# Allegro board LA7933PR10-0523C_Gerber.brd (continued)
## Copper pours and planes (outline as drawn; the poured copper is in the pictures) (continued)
+PWR_SRC on BOTTOM (solid shape): 191.74,50.61 191.74,48.07 191.62,47.94 191.54,47.94 190.17,47.94 190.17,47.94 189.84,47.94 188.57,46.67 184.89,46.67 184.38,46.17 182.42,46.17 182.28,46.3 182.28,49.53 188.31,49.53 188.32,49.47 188.33,49.42 188.35,49.37 188.38,49.32 188.41,49.28 188.45,49.24 188.5,49.2 188.55,49.18 188.6,49.16 188.65,49.15 188.71,49.15 188.76,49.15 188.82,49.17 188.87,49.19 188.92,49.22 188.96,49.26 189,49.3 189.03,49.34 189.05,49.39 189.07,49.45 189.08,49.5 189.08,49.56 189.07,49.61 189.05,49.67 189.03,49.72 189,49.76 188.96,49.81 188.92,49.84 188.87,49.87 188.82,49.89 188.76,49.91 188.71,49.91 188.65,49.91 188.6,49.9 188.55,49.88 188.5,49.86 188.45,49.82 188.41,49.79 188.38,49.74 188.35,49.69 188.33,49.64 188.32,49.59 188.31,49.53 182.28,49.53 182.28,49.91 183.11,50.74 191.62,50.74
+PWR_SRC on BOTTOM (solid shape): 145.68,109.1 145.68,107.13 145.49,106.94 145.47,106.94 145.34,106.81 145.34,106.81 145.3,106.76 144.18,106.76 144,106.94 142.98,106.94 142.47,106.43 142.47,104.97 141.71,104.21 136.36,104.21 136.33,104.18 133.4,104.18 132.68,104.91 132.68,107.94 132.83,108.09 144.64,108.09 144.64,108.03 144.65,107.98 144.67,107.93 144.7,107.88 144.74,107.84 144.78,107.8 144.82,107.76 144.87,107.74 144.92,107.72 144.98,107.71 145.03,107.71 145.09,107.71 145.14,107.73 145.19,107.75 145.24,107.78 145.28,107.82 145.32,107.86 145.35,107.9 145.38,107.95 145.39,108.01 145.4,108.06 145.4,108.12 145.39,108.17 145.38,108.23 145.35,108.28 145.32,108.32 145.28,108.37 145.24,108.4 145.19,108.43 145.14,108.45 145.09,108.47 145.03,108.47 144.98,108.47 144.92,108.46 144.87,108.44 144.82,108.42 144.78,108.38 144.74,108.35 144.7,108.3 144.67,108.25 144.65,108.2 144.64,108.15 144.64,108.09 132.83,108.09 133.13,108.39 135.59,108.39 136.85,109.65 145.13,109.65
+PWR_SRC on BOTTOM (solid shape): 24.74,147.64 24.74,147.1 24.72,147 24.74,146.9 24.74,144.84 24.32,144.42 19.03,144.42 19,144.43 18.99,144.44 18.73,144.56 18.45,144.47 18.39,144.45 18.07,144.57 17.75,144.45 17.69,144.47 17.28,144.53 17.05,144.19 17.05,144.17 17.05,143.57 16.99,143.51 16.18,143.51 16.16,143.52 16.16,144.06 16.69,144.06 16.71,144.08 16.71,144.81 16.22,144.81 16.17,144.85 16.17,145.28 16.7,145.28 16.72,145.3 16.72,145.31 16.72,146.05 16.18,146.05 16.16,146.07 16.16,146.81 16.22,146.87 17.13,146.87 17.24,146.75 17.25,146.73 17.36,146.48 17.61,146.37 17.63,146.37 17.75,146.24 19.66,146.24 21.18,147.77 24.61,147.77
+PWR_SRC on BOTTOM (solid shape): outline of 220 points within 181.84,16.19 192.63,25.97
+PWR_SRC on VCC (solid shape): outline of 800 points within 16.86,12.76 198.98,153.23
+PWR_SRC on IN2 (solid shape): outline of 3546 points within 23.34,140.77 79.34,151.12
+PWR_SRC on IN4 (solid shape): outline of 1805 points within 182.22,19.97 266.51,59.26
+PWR_SRC_MXM on TOP (solid shape): 188.9,173.15 188.9,167.89 188.62,167.62 186.64,167.62 185.55,168.71 185.55,174.24 185.79,174.49 187.56,174.49
+PWR_SRC_MXM on TOP (solid shape): 191.24,53.53 191.24,50.48 190.85,50.1 187.4,50.1 185.89,51.61 184.64,51.61 184.38,51.88 184.38,52.64 184.5,52.77 186.02,52.77 187.03,53.79 190.98,53.79
+PWR_SRC_MXM on BOTTOM (solid shape): 188.95,171.46 188.95,167.96 188.7,167.7 187.15,167.7 187.06,167.79 187.06,168.18 186.76,168.47 185.01,168.47 184.89,168.59 184.89,168.99 184.89,168.99 184.89,171.82 185.22,172.15 185.71,172.15 185.85,172.29 188.12,172.29
+PWR_SRC_MXM on BOTTOM (solid shape): outline of 241 points within 184.25,51.37 192.51,58.36
+PWR_SRC_MXM on IN1 (solid shape): outline of 13833 points within 184.5,49.8 221.94,173.2
+SDC_IN on TOP (solid shape): outline of 169 points within 3.15,85.59 12.79,93.54
+USB1_REPEATER_VDD on BOTTOM (solid shape): 262.5,67.51 262.5,67.24 262.49,67.2 262.45,67.19 261.97,67.19 261.97,66.75 262.45,66.75 262.49,66.74 262.5,66.7 262.5,66 261.6,65.1 261.6,63.8 261.39,63.58 260.62,63.58 259.59,64.61 259.59,67.45 259.8,67.66 262.36,67.66
+USB2_REPEATER_VDD on BOTTOM (solid shape): 254.65,69.25 254.65,68.31 255.16,67.8 256.86,67.8 257.79,68.73 258.33,68.73 258.53,68.53 258.53,67.93 257.24,66.64 257.24,66.21 256.97,65.94 255.82,65.94 255.14,65.26 255.14,63.62 255.55,63.21 257,63.21 257.42,62.78 257.42,61.72 257.19,61.48 255.41,61.48 254.15,62.74 254.15,66.6 254.17,66.63 254.2,66.65 254.68,66.65 254.68,67.08 254.2,67.08 254.17,67.1 254.15,67.13 254.15,68.01 254.12,68.04 253.26,68.9 252.83,68.9 252.79,68.94 252.79,69.49 252.83,69.53 254.37,69.53
+V_DDR_REF on BOTTOM (solid shape): 233.01,49.85 233.01,48.71 231.8,47.5 231.8,46.59 231.76,46.55 231.64,46.55 231.61,46.58 231.61,48.13 232.31,48.83 232.31,49.91 232.37,49.98 232.88,49.98
+VCHGR on TOP (solid shape): 188.7,32.58 188.7,31.69 188.57,31.56 186.92,31.56 186.79,31.43 186.79,30.8 186.92,30.67 188.67,30.67 188.69,30.65 188.7,30.63 188.86,30.36 189.16,30.3 189.17,30.3 189.2,30.29 189.84,29.66 189.84,22.67 190.47,22.04 192,22.04 192.12,21.91 192.12,17.21 191.87,16.96 188.57,16.96 188.31,17.21 188.31,20.64 185.39,23.56 185.39,32.58 185.52,32.7 188.57,32.7
+VCHGR_B on TOP (solid shape): 191.87,46.8 191.87,38.67 191.62,38.42 185.65,38.42 185.52,38.55 185.52,46.1 186.47,47.05 191.62,47.05
+VCHGR_B on BOTTOM (solid shape): 190.6,41.85 190.6,38.55 191.24,37.91 191.24,32.32 190.98,32.07 185.9,32.07 185.77,32.2 185.77,41.85 186.03,42.1 190.35,42.1
+VCHGR_L on TOP (solid shape): 192.63,37.91 192.63,32.32 192.25,31.94 192.25,30.16 192,29.91 189.84,29.91 189.58,30.16 189.58,30.42 189.71,30.54 191.24,30.54 191.36,30.67 191.36,31.31 191.24,31.43 189.63,31.43 189.6,31.45 189.58,31.48 189.58,32.83 189.33,33.08 187.3,33.08 187.04,33.34 187.04,37.91 187.17,38.04 192.51,38.04
+VDISPLAY_VCC on TOP (solid shape): 36.92,162.48 36.92,159.1 36.12,158.29 36.12,157.39 35.46,156.73 34.8,156.73 34.79,156.76 34.76,156.8 34.72,156.84 34.68,156.87 34.63,156.9 34.58,156.92 34.52,156.93 34.47,156.94 34.41,156.93 34.36,156.92 34.31,156.9 34.26,156.87 34.21,156.84 34.17,156.8 34.14,156.76 34.13,156.73 31.68,156.73 31.1,157.32 31.1,159.03 34.1,159.03 34.1,158.97 34.11,158.92 34.13,158.87 34.16,158.82 34.19,158.77 34.23,158.74 34.28,158.7 34.33,158.68 34.38,158.66 34.44,158.65 34.49,158.65 34.55,158.65 34.6,158.67 34.65,158.69 34.7,158.72 34.74,158.75 34.78,158.8 34.81,158.84 34.84,158.89 34.85,158.95 34.86,159 34.86,159.06 34.85,159.11 34.84,159.17 34.81,159.22 34.78,159.26 34.74,159.31 34.7,159.34 34.65,159.37 34.6,159.39 34.55,159.41 34.49,159.41 34.44,159.41 34.38,159.4 34.33,159.38 34.28,159.36 34.23,159.32 34.19,159.29 34.16,159.24 34.13,159.19 34.11,159.14 34.1,159.09 34.1,159.03 31.1,159.03 31.1,160.06 31.46,160.41 34.29,160.41 34.56,160.68 34.56,162.37 34.91,162.73 36.68,162.73
+VDISPLAY_VCC on IN2 (solid shape): outline of 196 points within 35.44,161.56 38.85,170.05
+VDISPLAY_VCC on IN3 (solid shape): outline of 196 points within 35.44,161.56 38.85,170.05
BOOT on TOP (solid shape): 179.3,37.78 179.3,37.02 179.11,36.83 178.54,36.83 177.48,35.78 176.86,35.78 176.5,35.42 176.5,33.33 176.49,33.29 176.45,33.27 176.3,33.27 176.26,33.29 176.25,33.33 176.25,36.51 176.44,36.7 177.46,36.7 177.96,37.21 177.96,37.85 178.03,37.91 179.17,37.91
BOOT1 on TOP (solid shape): 28.99,76.71 28.99,76.26 29.25,76.01 30.25,76.01 31.41,76.01 31.91,76.52 32.49,76.52 32.61,76.39 32.61,75.38 32.36,75.12 29.95,75.12 29.56,75.5 29.1,75.5 28.74,75.86 28.74,76.71 28.8,76.77 28.93,76.77
BOOT1G on TOP (solid shape): 31.34,84.46 31.34,83.25 28.99,80.9 28.8,80.9 28.8,81.73 28.93,81.85 29.31,81.85 30.2,82.74 30.2,83.88 30.07,84.01 30.07,84.52 30.2,84.65 31.15,84.65
BOOT2 on TOP (solid shape): 32.54,83.13 32.54,82.16 32.36,81.98 30.83,81.98 30.01,81.15 30.01,80.77 30.07,80.71 30.07,80.58 30.01,80.52 29.12,80.52 29.06,80.58 29.06,80.65 29.12,80.71 29.18,80.71 29.37,80.9 29.37,81.09 31.53,83.25 32.42,83.25
BOOT2G on TOP (solid shape): 27.99,88.77 28.07,88.77 28.57,88.27 29.31,88.27 29.39,88.19 29.39,88.08 29.31,88 28.41,88 28.14,88.27 27.76,88.27 27.7,88.33 26.77,88.33 26.52,88.58 26.52,88.96 26.85,89.29 27.47,89.29
BOOT3 on BOTTOM (solid shape): 49.06,45.15 49.06,44.32 48.93,44.2 47.8,44.2 47.55,44.45 45.95,44.45 45.88,44.51 45.88,44.71 45.95,44.77 46.96,44.77 47.47,45.28 48.93,45.28
BOOT_1.5V on BOTTOM (solid shape): 229.2,45.66 230.26,45.66 230.27,45.64 230.27,45.44 230.23,45.4 228.48,45.4 228.18,45.1 228.18,44.34 228,44.16 227.29,44.16 227.16,44.29 227.16,45.5 227.37,45.71 229.14,45.71
BST1_3V on BOTTOM (solid shape): 283.63,60.52 283.63,57.66 283.5,57.53 282.68,57.53 282.48,57.72 282.48,60.58 282.61,60.71 283.44,60.71
BST1_5V on BOTTOM (solid shape): 270.42,61.34 270.42,58.61 270.17,58.36 269.53,58.36 269.34,58.55 269.34,61.28 269.53,61.47 270.29,61.47
BST_3V on BOTTOM (solid shape): 282.04,60.45 282.04,59.44 281.91,59.31 280.45,59.31 280.12,59.65 280.12,60.23 279.96,60.39 277.79,60.39 277.72,60.45 277.72,60.58 277.79,60.64 281.85,60.64
BST_5V on BOTTOM (solid shape): 273.21,60.64 274.67,60.64 274.67,60.39 271.98,60.39 271.73,60.14 270.99,60.14 270.86,60.26 270.86,61.34 270.99,61.47 272.39,61.47
BST_+V1.05S_VCCPP on BOTTOM (solid shape): 61.43,22.81 61.44,22.8 61.44,22.78 61.44,22.66 62.08,22.02 62.08,20.32 61.95,20.19 61.12,20.19 60.87,20.45 60.87,22.29 60.49,22.67 60.49,22.92 60.55,22.99 61.25,22.99
BST_+V1.05SP on TOP (solid shape): 5.88,152.02 5.88,151.89 6.83,150.94 7.15,150.94 7.34,150.75 7.34,150.11 7.15,149.92 6.2,149.92 6.07,150.05 6.07,150.44 6.2,150.57 6.2,151.06 5.99,151.26 5.61,151.26 5.56,151.31 5.56,152.08 5.62,152.15 5.75,152.15
CD3301_DCIN on TOP (solid shape): 175.02,69.85 175.02,68.5 174.96,68.45 174.96,68.09 174.79,67.92 174.79,66.68 174.41,66.29 171.42,66.29 171.3,66.42 171.3,67.5 171.49,67.69 173.58,67.69 174.73,68.83 174.73,69.86 174.78,69.91 174.95,69.91
CHG_LGATE on BOTTOM (solid shape): 193.52,35.24 193.52,34.99 193.52,34.9 193.6,34.82 194.26,34.82 194.33,34.75 194.33,34.09 194.21,33.96 193.56,33.96 192.66,34.86 191.87,34.86 191.74,34.99 191.74,35.24 191.87,35.37 193.39,35.37
CHG_SNUB on BOTTOM (solid shape): 193.39,33.72 195.72,33.72 195.78,33.66 195.78,32.69 195.53,32.44 193.25,32.44 192.89,32.07 192.12,32.07 191.87,32.32 191.87,33.85 192.12,34.1 193.01,34.1
CHG_UGATE on BOTTOM (solid shape): 190.09,43.12 190.09,42.48 189.97,42.36 186.28,42.36 186.16,42.48 186.16,43.12 186.28,43.24 189.97,43.24
CHG_UGATE on BOTTOM (solid shape): 177.39,36.16 177.39,34.56 177.27,34.43 176.6,34.43 176.48,34.56 176.48,36.16 176.55,36.23 177.32,36.23
DH_1.5V on BOTTOM (solid shape): 221.7,41.17 221.7,39.9 221.58,39.78 220.56,39.78 220.31,40.03 220.31,41.17 220.43,41.3 221.58,41.3
DH_1.5V on BOTTOM (solid shape): 229.29,45.24 230.25,45.24 230.27,45.22 230.27,45.05 230.23,45.01 229.31,45.01 228.94,44.64 228.94,44.63 228.94,44.2 228.88,44.13 228.43,44.13 228.37,44.2 228.37,45.02 228.62,45.28 229.26,45.28
DH_1.5V on IN3 (solid shape): 229.17,45.5 229.17,44.36 228.92,44.11 227.9,44.11 227.65,44.36 227.65,45.5 227.77,45.63 229.04,45.63
DH_1.5V on IN3 (solid shape): 221.89,41.49 221.89,40.07 221.73,39.9 220.69,39.9 220.43,40.16 220.43,41.44 220.79,41.8 221.59,41.8
DL_1.5V on BOTTOM (solid shape): 222.99,35.68 222.99,33.54 222.86,33.42 221.5,33.42 221.42,33.49 221.42,35.66 221.72,35.95 222.72,35.95
DL_1.5V on BOTTOM (solid shape): 230.61,44.49 230.61,43.58 230.34,43.31 230.34,42.18 230.34,42.17 230.34,41.78 230.27,41.72 229.32,41.72 229.2,41.85 229.2,42.93 230.4,44.13 230.4,44.49 230.44,44.54 230.56,44.54
DL_1.5V on IN1 (solid shape): 223.32,34.82 223.32,33.89 223.11,33.68 221.68,33.68 221.51,33.84 221.51,34.8 221.65,34.94 223.2,34.94
DL_1.5V on IN1 (solid shape): 230.34,42.55 230.34,41.4 230.21,41.28 228.56,41.28 228.5,41.34 228.5,42.42 228.69,42.61 229.51,42.61 229.58,42.67 230.21,42.67
ERC1 on TOP (solid shape): 176,68.75 176.12,68.62 176.12,67.19 176.25,67.06 176.25,66.49 176.12,66.36 175.17,66.36 174.98,66.55 174.98,67.17 175.86,68.05 175.86,68.61 175.74,68.72 175.74,69.72 176,69.72
ERC3 on TOP (solid shape): 182.35,71.37 182.35,70.23 182.12,70 181.41,70 181.28,70.13 181.28,70.76 180.99,71.05 180.7,71.05 180.69,71.06 179.23,71.06 179.23,71.31 180.88,71.31 181.08,71.5 182.22,71.5
GP1_SW on TOP (solid shape): 46.58,84.29 46.58,81.27 46.46,81.14 45.19,81.14 45.06,81.01 45.06,80.76 45.19,80.63 46.46,80.63 46.58,80.5 46.58,79.69 46.46,79.57 43.41,79.57 43.15,79.82 43.15,80.76 42.9,81.01 41.5,81.01 41.38,81.14 41.38,84.44 41.57,84.63 46.24,84.63
GP2_SW on TOP (solid shape): 46.71,90.75 46.71,88.63 46.58,88.5 45.06,88.5 45.06,88 46.58,88 46.71,87.87 46.71,87.06 46.54,86.89 43.56,86.89 43.47,86.98 41.5,86.98 41.38,87.11 41.38,90.77 41.53,90.93 46.54,90.93
LG_3V on BOTTOM (solid shape): 279.25,58.61 279.25,58.36 279.12,58.23 278.17,58.23 277.72,58.67 277.72,59.06 277.79,59.12 278.74,59.12
LG_3V on BOTTOM (solid shape): 276.05,49.4 276.05,48.32 275.99,48.27 274.13,48.27 274.04,48.36 274.04,49.29 274.22,49.47 275.98,49.47
LG_3V on IN3 (solid shape): 276.58,49.47 276.58,48.71 276.45,48.58 274.17,48.58 274.04,48.71 274.04,49.59 274.17,49.72 276.33,49.72
LG_3V on IN3 (solid shape): 279.37,58.48 279.37,57.72 279.25,57.6 277.98,57.6 277.85,57.72 277.85,58.74 277.98,58.87 278.99,58.87
LG_5V on BOTTOM (solid shape): 270.1,46.42 270.1,45.66 269.9,45.45 268.88,45.45 268.68,45.66 267.79,45.66 267.51,45.94 267.51,46.58 267.6,46.67 269.85,46.67
LG_5V on BOTTOM (solid shape): 274.74,59.11 274.74,58.87 274.61,58.74 274.61,58.23 274.55,58.17 273.47,58.17 273.4,58.23 273.4,58.9 273.67,59.17 274.67,59.17
LG_5V on IN3 (solid shape): 274.67,58.61 274.67,57.47 274.55,57.34 273.4,57.34 273.28,57.47 273.28,58.61 273.4,58.74 274.55,58.74
LG_5V on IN3 (solid shape): 270.1,46.8 270.1,45.66 269.9,45.45 268.78,45.45 268.58,45.66 268.58,46.93 268.71,47.05 269.85,47.05
LG_+V1.05S_VCCPP on TOP (solid shape): 67.05,20.77 67.05,20.02 66.97,19.93 65.75,19.93 65.61,20.07 65.61,20.74 65.76,20.89 66.93,20.89
LG_+V1.05S_VCCPP on BOTTOM (solid shape): 61.76,25.59 61.76,25.15 61.31,24.7 60.55,24.7 60.45,24.8 60.45,25.53 60.58,25.65 61.7,25.65
LG_+V1.05S_VCCPP on BOTTOM (solid shape): 67.41,20.21 67.41,19.5 67.28,19.37 65.4,19.37 65.33,19.44 65.33,19.93 66,20.6 67.02,20.6
LG_+V1.05SP on TOP (solid shape): 3.85,152.08 3.85,151.45 3.78,151.38 2.36,151.38 2.26,151.49 2.26,152.07 2.34,152.15 3.78,152.15
LG_+V1.05SP on BOTTOM (solid shape): 9.09,141.58 9.09,140.17 9.07,140.15 8.49,140.15 7.86,140.78 6.96,140.78 6.83,140.91 6.83,141.29 6.96,141.42 7.82,141.42 8.04,141.64 8.69,141.64 8.72,141.68 9,141.68
LG_+V1.05SP on IN1 (solid shape): 3.44,152.02 3.44,151.36 3.14,151.05 1.81,151.05 1.33,151.54 1.33,152.13 1.56,152.36 3.1,152.36
LG_+V1.05SP on IN1 (solid shape): 9.1,141.55 9.1,141.19 8.65,140.73 7.55,140.73 7.47,140.82 7.47,141.33 7.73,141.59 8.56,141.59 8.66,141.69 8.96,141.69
LGATE1 on TOP (solid shape): 43.03,62.85 43.03,61.96 42.9,61.83 41.5,61.83 41.38,61.96 41.38,62.85 41.5,62.98 42.9,62.98
LGATE1 on TOP (solid shape): 43.79,56.88 43.79,56.12 43.66,55.99 41.5,55.99 41.38,56.12 41.38,56.88 41.5,57.01 43.66,57.01
LGATE1 on TOP (solid shape): 30.52,77.72 30.89,77.72 31.48,77.72 31.52,77.71 31.53,77.67 31.53,77.22 31.47,77.15 30.64,77.15 30.07,77.72 29.17,77.72 29.13,77.74 29.12,77.78 29.12,77.86 29.13,77.9 29.17,77.92 30.33,77.92
LGATE1 on BOTTOM (solid shape): 43.78,57.72 43.78,56.59 43.62,56.44 42.65,56.44 42.45,56.63 42.45,57.54 42.71,57.8 43.7,57.8
LGATE1 on BOTTOM (solid shape): 43.09,62.97 43.09,62 42.96,61.87 41.64,61.87 41.54,61.98 41.54,62.95 41.6,63.02 43.04,63.02
LGATE1 on IN1 (solid shape): 43.4,63.57 43.4,62.67 43.41,62.66 43.41,57.72 43.92,57.21 43.92,56.58 43.71,56.37 41.88,56.37 41.76,56.5 41.76,63.56 42.01,63.82 43.15,63.82
LGATE1 on IN1 (solid shape): 30.51,77.78 30.71,77.72 30.92,77.79 32.23,77.79 32.36,77.66 32.36,77.03 32.23,76.9 30.45,76.9 30.33,77.03 30.33,77.66 30.45,77.79 30.49,77.79
LGATE1G on TOP (solid shape): 28.17,83.5 28.17,82.55 27.85,82.23 27.85,81.79 27.72,81.66 27.72,80.9 27.6,80.9 27.6,83.44 27.72,83.57 28.1,83.57
LGATE1G on TOP (solid shape): 42.61,80.53 42.59,80.52 42.59,79.31 42.39,79.11 41.5,79.11 41.38,79.23 41.38,80.5 41.5,80.63 42.51,80.63
LGATE1G on BOTTOM (solid shape): 42.51,80.35 42.51,79.11 42.4,79.01 41.55,79.01 41.38,79.19 41.38,80.37 41.53,80.52 42.34,80.52
LGATE1G on IN3 (solid shape): 42.65,79.74 42.65,78.85 42.52,78.73 40.49,78.73 40.36,78.85 40.36,79.74 40.49,79.87 42.52,79.87
LGATE1G on IN3 (solid shape): 28.56,84.51 28.56,83.83 28.17,83.44 28.17,82.49 28.04,82.36 27.66,82.36 27.57,82.45 27.55,82.48 27.56,82.51 27.6,82.7 27.53,82.89 27.53,83.29 27.7,83.45 27.7,83.88 27.53,84.05 27.53,84.77 27.66,84.9 28.17,84.9
LGATE2 on TOP (solid shape): 42.65,74.41 42.65,73.14 42.52,73.01 41.38,73.01 41.25,73.14 41.25,74.41 41.38,74.53 42.52,74.53
LGATE2 on TOP (solid shape): 42.65,68.49 42.65,67.17 42.52,67.04 41.38,67.04 41.25,67.17 41.25,67.88 41.25,67.88 41.25,68.48 41.48,68.71 42.42,68.71
LGATE2 on TOP (solid shape): 31.6,79.76 31.6,79.5 31.47,79.38 30.96,79.38 30.83,79.25 30.45,79.25 30.39,79.31 29.12,79.31 29.12,79.5 30.33,79.5 30.71,79.88 31.47,79.88
LGATE2 on BOTTOM (solid shape): 42.58,68.47 42.58,67.26 42.4,67.08 41.46,67.08 41.25,67.3 41.25,68.44 41.38,68.57 42.48,68.57
LGATE2 on BOTTOM (solid shape): 43.41,73.75 43.41,72.75 43.18,72.52 41.62,72.52 41.16,72.97 41.16,73.83 41.21,73.88 43.28,73.88
LGATE2 on IN1 (solid shape): 42.65,73.39 42.65,67.3 42.39,67.04 41.25,67.04 41.12,67.17 41.12,72.63 40.99,72.76 40.23,72.76 40.11,72.88 40.11,73.52 40.23,73.65 42.39,73.65
LGATE2 on IN1 (solid shape): 32.8,79.44 32.8,78.99 32.68,78.87 32.1,78.87 31.6,79.38 30.96,79.38 30.83,79.25 30.52,79.25 30.39,79.38 30.39,79.76 30.52,79.88 32.36,79.88
LGATE2G on TOP (solid shape): 42.65,86.59 42.65,85.34 42.52,85.2 41.5,85.2 41.38,85.33 41.38,86.6 41.5,86.73 42.52,86.73
LGATE2G on TOP (solid shape): 31.72,87.16 31.72,86.36 31.6,86.23 30.45,86.23 30.33,86.36 30.33,86.59 30.55,86.82 30.55,86.93 30.55,86.94 30.55,87.21 30.66,87.31 31.57,87.31
LGATE2G on BOTTOM (solid shape): 42.81,86.37 42.81,85.32 42.63,85.14 41.69,85.14 41.51,85.32 41.51,85.64 41.57,85.69 41.81,85.69 41.91,85.79 41.91,86.39 41.96,86.44 42.75,86.44
LGATE2G on IN3 (solid shape): 42.65,85.84 42.65,84.95 42.52,84.82 40.87,84.82 40.74,84.95 40.74,85.84 40.87,85.96 42.52,85.96
LGATE2G on IN3 (solid shape): 32.61,87.06 32.61,86.31 32.57,86.23 32.48,86.21 32.23,86.21 32.04,86.07 32.02,86.05 32,86.04 30.45,86.04 30.33,86.17 30.33,87.19 30.45,87.31 32.36,87.31
LGATE3 on TOP (solid shape): 52.04,54.62 52.04,53.7 51.79,53.45 50.65,53.45 50.39,53.71 50.39,54.43 50.65,54.69 51.97,54.69
LGATE3 on TOP (solid shape): 46.33,54.64 46.33,53.83 46.07,53.58 44.8,53.58 44.68,53.71 44.68,54.6 44.95,54.87 46.09,54.87
LGATE3 on BOTTOM (solid shape): 51.93,54.48 51.93,53.63 51.57,53.28 50.79,53.28 50.72,53.34 50.72,54.24 51.1,54.62 51.79,54.62
LGATE3 on BOTTOM (solid shape): 44.74,43.75 44.74,43.31 44.68,43.24 44.3,43.24 43.89,42.84 43.32,42.84 43.03,43.13 43.03,43.75 43.09,43.82 44.68,43.82
LGATE3 on BOTTOM (solid shape): 46.71,55.07 46.71,53.98 46.43,53.7 45.77,53.7 45.6,53.86 45.6,54.09 45.4,54.29 44.82,54.29 44.65,54.46 44.65,55.19 44.72,55.26 46.52,55.26
LGATE3 on IN1 (solid shape): 44.11,44.13 44.11,42.98 43.97,42.84 43.17,42.84 42.92,43.08 42.92,44.06 43.09,44.22 44.02,44.22
LGATE3 on IN1 (solid shape): 52.11,54.74 52.11,53.59 51.92,53.4 51.22,53.4 50.96,53.66 46.71,53.66 46.52,53.47 46.52,52.71 46.39,52.58 45.57,52.58 45.44,52.71 45.44,54.86 45.57,54.99 51.85,54.99
LX_3V on TOP (solid shape): 283.89,50.32 283.89,49.87 283.31,49.29 281.91,49.29 281.77,49.43 281.77,49.78 282.36,50.37 283.84,50.37
LX_3V on TOP (solid shape): 282.81,57.06 282.81,56.6 282.51,56.3 281.75,56.3 281.01,57.04 281.01,57.42 281.14,57.54 282.33,57.54
LX_3V on BOTTOM (solid shape): 280.01,58.93 282.08,58.93 282.23,58.78 282.23,57.05 282.12,56.93 281.11,56.93 278.67,59.37 277.79,59.37 277.72,59.44 277.72,59.56 277.79,59.63 279.31,59.63
LX_3V on BOTTOM (solid shape): 285.34,51.63 285.34,48.83 286.61,47.56 286.61,44.26 285.64,43.29 278.53,43.29 277.89,43.93 276.82,43.93 276.58,44.17 276.58,48.96 276.71,49.09 281.53,49.09 281.66,49.21 281.66,50.36 281.53,50.48 280.39,50.48 280.14,50.74 280.14,52.39 280.39,52.64 284.33,52.64
LX_5V on TOP (solid shape): 264.83,51.36 264.83,50.25 264.64,50.06 263.97,50.06 263.76,50.27 263.76,51.35 263.9,51.49 264.7,51.49
LX_5V on TOP (solid shape): 272.93,59.33 272.93,58.84 272.16,58.06 271.55,58.06 271.5,58.12 271.5,58.94 272,59.44 272.82,59.44
LX_5V on BOTTOM (solid shape): 274.78,59.56 274.78,59.45 274.72,59.4 273.68,59.4 273.53,59.25 273.15,59.25 272.26,58.36 270.99,58.36 270.86,58.48 270.86,59.44 271.05,59.63 274.71,59.63
LX_5V on BOTTOM (solid shape): 265.78,51.88 265.78,49.47 266.17,49.09 266.72,49.09 267.03,48.78 267.03,45.82 266.17,44.96 266.17,41.59 266.04,41.47 262.23,41.47 261.21,42.48 261.21,47.05 260.83,47.44 260.83,51.63 261.21,52.01 265.66,52.01
MAX8731A_LDO on TOP (solid shape): 180.92,32.96 180.96,32.96 181.64,32.96 181.64,32.96 181.89,32.96 182.07,32.78 182.07,31.92 182.47,31.51 182.47,31.13 182.4,31.05 182.16,31.05 182.14,31.03 181.46,31.03 180.95,31.53 180.95,31.76 180.95,31.76 180.95,32.12 180.95,32.2 180.24,32.91 179.55,32.91 179.35,32.7 178.33,32.7 178.3,32.72 178.28,32.75 178.28,32.88 178.3,32.92 178.33,32.93 179.04,32.93 179.5,33.39 180.49,33.39
Net_85 on TOP (solid shape): 282.95,10.62 282.95,6.87 283.07,6.75 283.07,2.28 282.98,2.19 282.22,2.19 282.06,2.35 282.06,6.69 282.16,6.79 282.16,10.67 282.17,10.68 282.89,10.68
P1_SW on TOP (solid shape): 46.58,67.93 46.58,66.79 46.46,66.66 45.31,66.66 45.19,66.53 45.19,66.28 45.31,66.15 46.46,66.15 46.58,66.03 46.58,65.06 46.55,64.99 46.48,64.96 46.33,64.94 46.2,64.87 46.14,64.84 46.07,64.87 45.55,64.85 45.53,64.33 45.56,64.26 45.53,64.2 45.84,63.56 46.08,64.23 46.06,64.26 46.08,64.3 46.1,64.32 46.14,64.34 46.17,64.32 46.31,64.23 46.48,64.2 46.55,64.17 46.58,64.1 46.58,61.07 46.33,60.82 43.61,60.82 43.53,60.82 43.28,60.56 43.28,57.64 43.03,57.39 41.63,57.39 41.38,57.64 41.38,61.15 41.93,61.71 43.03,61.71 43.15,61.83 43.15,63.1 43.03,63.23 41.5,63.23 41.38,63.36 41.38,66.66 41.5,66.79 42.77,66.79 42.9,66.91 42.9,67.93 43.03,68.06 46.46,68.06
P2_SW on TOP (solid shape): outline of 133 points within 41.25,68.62 46.71,78.78
P3_SW on TOP (solid shape): 46.46,60.52 46.46,59.75 46.38,59.68 45.57,59.68 45.31,59.42 45.31,59.04 45.44,58.91 46.28,58.91 46.46,58.74 46.46,57.39 46.65,57.2 48.55,57.2 49.63,56.12 49.66,56.03 49.6,55.96 49.4,55.47 49.88,55.25 49.97,55.23 50.01,55.15 50.01,53.71 49.88,53.58 46.58,53.58 46.46,53.71 46.46,53.78 46.46,54.77 46.19,55.04 44.86,55.04 44.3,54.47 44.3,53.83 44.04,53.58 40.99,53.58 40.74,53.83 40.74,55.48 40.99,55.74 43.84,55.74 44.04,55.94 44.04,56.83 43.41,57.47 43.41,60.41 43.41,60.44 43.66,60.69 46.28,60.69
PBATT+ on TOP (solid shape): outline of 191 points within 181.58,5.02 188.06,21.91
PBATT+_C on TOP (solid shape): 191.24,10.1 191.24,8.7 191.11,8.57 190.35,8.57 190.22,8.45 190.22,7.05 190.35,6.92 191.49,6.92 191.74,6.67 191.74,5.53 192.12,5.14 192.12,1.59 191.87,1.33 187.93,1.33 187.81,1.46 187.81,5.34 187.81,5.35 187.81,10.1 188.06,10.35 190.98,10.35
PBATT_IN_SS on TOP (solid shape): 195.3,16.07 195.3,11.24 194.92,10.86 187.55,10.86 187.17,11.24 187.17,16.07 187.43,16.32 195.05,16.32
PBATT_IN_SS on BOTTOM (solid shape): 194.16,19.11 194.16,18.23 195.05,17.34 196.32,17.34 196.44,17.21 196.44,11.24 196.06,10.86 184.63,10.86 184.25,11.24 184.25,15.56 184.63,15.94 188.31,15.94 189.2,16.83 189.2,18.99 189.58,19.37 193.9,19.37
PHASE1 on TOP (solid shape): 35.67,62.85 36.93,62.85 37.06,62.72 37.06,62.09 36.93,61.96 35.02,61.96 34.77,62.21 34.77,62.72 34.99,62.94 35.58,62.94
PHASE1 on TOP (solid shape): 37.06,57.14 37.06,56.25 36.8,55.99 35.41,55.99 35.39,56.01 34.99,56.01 34.82,56.19 34.82,57.18 34.9,57.26 36.93,57.26
PHASE1 on TOP (solid shape): 32.68,77.85 32.68,76.96 32.42,76.71 31.72,76.71 31.6,76.58 31.6,76.39 31.41,76.2 30.58,76.2 30.39,76.39 30.39,76.63 30.2,76.82 30.2,77.08 30.14,77.14 30.14,77.15 30.01,77.28 29.17,77.28 29.13,77.29 29.12,77.33 29.12,77.42 29.13,77.46 29.17,77.47 30.14,77.47 30.3,77.31 30.3,77.3 30.37,77.2 30.47,77.13 30.48,77.13 30.58,77.03 31.53,77.03 31.66,77.15 31.66,77.85 31.85,78.04 32.49,78.04
PHASE1 on IN1 (solid shape): 37.23,62.59 37.23,56.23 36.68,55.67 34.42,55.67 34.03,56.06 34.03,57.07 34.26,57.3 35.81,57.3 36.04,57.53 36.04,60.11 36.07,60.25 36.04,60.39 36.04,61.14 35.84,61.34 34.68,61.34 34.5,61.52 34.5,62.53 34.69,62.72 37.1,62.72
PHASE1 on IN3 (solid shape): 31.72,76.65 31.72,75.12 31.6,74.99 30.58,74.99 30.45,75.12 30.45,76.65 30.58,76.77 31.6,76.77
PHASE1 on IN3 (solid shape): 35.34,63.63 35.35,63.6 35.34,63.57 35.36,63.13 35.78,63 35.87,62.98 35.91,62.9 35.91,62.17 35.79,62.04 34.9,62.04 34.14,62.8 34.14,63.44 34.39,63.69 35.28,63.69
PHASE1G on TOP (solid shape): 37.06,80.5 37.06,79.74 36.8,79.49 34.64,79.49 34.52,79.61 34.52,80.25 34.64,80.38 35.91,80.38 36.17,80.63 36.93,80.63
PHASE1G on TOP (solid shape): 29.18,84.65 29.18,82.8 28.8,82.42 28.61,82.42 28.17,81.98 28.17,80.9 27.98,80.9 27.98,82.17 28.29,82.49 28.29,83.57 27.85,84.01 27.85,84.52 28.04,84.71 29.12,84.71
PHASE1G on IN4 (solid shape): 29.06,83.5 29.06,83 29.18,82.87 29.82,82.87 29.95,82.74 29.95,81.98 29.82,81.85 28.68,81.85 28.29,82.23 28.29,83.5 28.42,83.63 28.93,83.63
PHASE1G on IN4 (solid shape): 34.52,80.33 35.79,80.33 35.91,80.2 35.91,79.57 35.79,79.44 34.67,79.44 34.42,79.53 34.16,79.44 34.01,79.44 33.5,79.95 33.5,80.46 33.76,80.71 34.14,80.71
PHASE2 on TOP (solid shape): 36.93,68.69 36.93,67.93 36.8,67.8 34.77,67.8 34.52,68.06 34.52,68.69 34.64,68.82 36.8,68.82
PHASE2 on TOP (solid shape): 37.06,74.53 37.06,73.77 36.93,73.65 34.77,73.65 34.64,73.77 34.64,74.53 34.77,74.66 36.93,74.66
PHASE2 on TOP (solid shape): 32.68,81.6 32.68,80.77 32.36,80.46 31.79,80.46 31.34,80.01 30.64,80.01 30.33,79.69 29.12,79.69 29.12,79.88 30.2,79.88 31.28,80.96 31.28,81.66 31.41,81.79 32.49,81.79
PHASE2 on IN3 (solid shape): 32.61,80.65 32.61,80.14 32.49,80.01 30.77,80.01 30.64,80.14 30.64,80.39 31.02,80.77 32.49,80.77
PHASE2 on IN3 (solid shape): 34.3,75.71 34.3,74.98 34.54,74.74 37.06,74.74 37.44,74.36 37.44,68.64 36.55,67.76 36.23,67.76 36.22,67.76 36.04,67.8 35.87,67.76 35.85,67.76 34.78,67.76 34.52,68.02 34.52,68.77 34.64,68.9 35.79,68.9 36.17,69.28 36.17,73.47 35.91,73.72 33.7,73.72 33.02,74.41 33.02,75.69 33.21,75.88 34.12,75.88
PHASE2G on TOP (solid shape): 37.06,86.6 37.06,85.96 36.93,85.84 34.52,85.84 34.39,85.96 34.39,86.85 34.52,86.98 36.68,86.98
PHASE2G on TOP (solid shape): 31.58,90.23 31.58,88.73 31.34,88.49 30.64,88.49 30.55,88.58 30.55,88.77 30.43,88.89 30.03,88.89 29.73,89.19 29.73,89.71 29.56,89.88 29.56,90.74 29.82,91 30.82,91
PHASE2G on IN1 (solid shape): 31.52,89.83 31.52,89.13 31.46,89.07 30.26,89.07 30.06,89.27 30.06,89.78 30.16,89.88 31.47,89.88
PHASE2G on IN1 (solid shape): 35.93,86.82 35.93,86.09 35.86,86.03 34.69,86.03 34.53,86.2 34.53,86.79 34.75,87.01 35.74,87.01
PHASE3 on TOP (solid shape): 51.28,49.13 51.28,46.98 51.15,46.85 50.39,46.85 50.27,46.98 50.27,49.13 50.39,49.26 51.15,49.26
PHASE3 on TOP (solid shape): 45.68,49.09 45.68,47.59 45.59,47.5 44.63,47.5 44.55,47.57 44.55,49.09 44.68,49.21 45.55,49.21
PHASE3 on BOTTOM (solid shape): 46.39,48.07 46.39,47.63 46.17,47.41 46.14,47.37 46.1,47.33 45.57,46.8 45.57,46.48 44.74,45.66 44.74,45.29 44.74,45.09 44.61,44.96 43.85,44.96 43.79,45.02 43.79,46.42 44.55,47.18 44.55,47.88 44.87,48.2 46.27,48.2
PHASE3 on IN3 (solid shape): 50.96,49.21 50.96,46.86 50.9,46.8 50.33,46.8 50.14,46.99 50.14,48.13 50.01,48.26 46.98,48.26 46.07,47.36 44.65,47.36 44.45,47.56 44.45,48.18 44.63,48.36 45.16,48.36 46.14,49.34 50.84,49.34
PWMG2 on TOP (solid shape): 27.47,82.8 27.47,81.85 27.34,81.73 27.34,80.9 27.15,80.9 27.15,82.3 26.96,82.49 26.96,82.87 27.02,82.93 27.34,82.93
PWMG2 on TOP (solid shape): 28.2,87.99 28.2,87.92 28.34,87.77 29.31,87.77 29.37,87.71 29.37,87.55 29.32,87.5 27.51,87.5 27.47,87.54 27.47,87.99 27.61,88.13 28.06,88.13
SNUB_1.5V on BOTTOM (solid shape): 229.75,34.52 229.75,31.38 229.34,30.96 228.01,30.96 227.82,31.15 227.82,34.51 228.08,34.76 229.51,34.76
SNUB_1.5VSP on BOTTOM (solid shape): 211.43,69.03 211.43,68.26 211.3,68.14 207.75,68.14 207.62,68.26 207.62,69.15 207.75,69.28 211.17,69.28
SNUB_3V on BOTTOM (solid shape): 278.69,41.99 278.69,41.48 278.43,41.22 276.78,41.22 275,43 275,43.51 275.26,43.76 276.91,43.76
SNUB_5V on BOTTOM (solid shape): 268.31,45.03 269.71,45.03 269.96,44.78 269.96,43.64 269.84,43.51 267.04,43.51 266.91,43.64 266.91,45.03 267.17,45.29 268.06,45.29
SNUB_+V1.05SP on BOTTOM (solid shape): 8.46,139.89 9.57,139.89 9.57,139.89 11.58,139.89 11.76,139.71 11.76,138.66 11.61,138.51 10.38,138.51 10.01,138.76 9.63,138.51 9.31,138.18 7.31,138.18 6.92,138.57 6.92,139.68 7.31,140.07 8.28,140.07
SW_1.5V on BOTTOM (solid shape): 230.27,44.83 230.27,44.63 230.22,44.58 230.22,44.39 228.28,42.46 227.37,42.46 227.16,42.66 227.16,43.69 227.37,43.9 228.83,43.9 229.07,44.13 229.07,44.58 229.33,44.84 230.26,44.84
SW_1.5V on BOTTOM (solid shape): 224.41,47.75 224.41,44.51 225.61,43.31 225.61,43.07 225.84,42.61 226.35,42.53 226.37,42.54 226.4,42.52 229.8,39.12 229.8,37.07 229.4,36.67 222.36,36.67 222.17,36.86 222.17,41.19 221.83,41.52 219.81,41.52 219.68,41.4 219.68,40.01 219.57,39.9 216.4,39.9 216.08,40.22 216.08,43.23 218.41,45.57 218.41,48.2 219,48.78 223.38,48.78
SW_1.5V on IN4 (solid shape): 229.34,43.79 229.34,43.29 228.59,42.55 228.04,42.55 227.68,42.91 227.68,43.58 228,43.9 229.22,43.9
SW_1.5V on IN4 (solid shape): 225.17,42.89 225.17,42.11 224.94,41.89 223.24,41.89 223.1,42.02 223.1,42.95 223.16,43.02 225.04,43.02
SW_+V1.05S_VCCPP on TOP (solid shape): 71.8,15.2 71.8,14.59 71.65,14.44 69.92,14.44 69.9,14.47 69.9,15.25 69.94,15.29 71.72,15.29
SW_+V1.05S_VCCPP on TOP (solid shape): 63.9,24 63.9,23.37 63.74,23.2 63.1,23.2 62.83,23.48 61.63,23.48 61.47,23.65 61.47,24.05 61.54,24.13 63.78,24.13
SW_+V1.05S_VCCPP on BOTTOM (solid shape): 71.35,22.54 71.35,18.48 71.73,18.1 75.79,18.1 76.43,17.46 76.43,14.16 76.17,13.91 71.89,13.91 71.51,14.29 69.32,14.29 69.06,14.54 69.06,16.32 68.81,16.57 68.05,16.57 67.92,16.7 67.92,22.67 68.05,22.8 71.09,22.8
SW_+V1.05S_VCCPP on BOTTOM (solid shape): 64.08,24.04 64.08,23.44 63.94,23.31 62.01,23.31 61.57,23.75 60.67,23.75 60.63,23.76 60.62,23.8 60.62,23.95 60.63,23.99 60.67,24 62.27,24 62.46,24.19 63.93,24.19
SW_+V1.05SP on TOP (solid shape): 7.72,148.15 7.72,146.24 7.69,146.22 7.69,145.56 7.15,145.01 4.08,145.01 3.91,144.84 3.91,142.83 3.63,142.55 2.29,142.55 2.13,142.71 2.13,147.51 2.89,148.27 7.59,148.27
SW_+V1.05SP on TOP (solid shape): 4.81,152.08 4.85,152.07 4.86,152.03 4.86,151.13 5.12,150.88 5.18,150.88 5.56,150.5 5.56,149.8 5.43,149.67 3.85,149.67 3.78,149.73 3.78,150.05 4.29,150.56 4.29,150.88 4.61,151.19 4.61,152.03 4.62,152.07 4.66,152.08
SW_+V1.05SP on BOTTOM (solid shape): outline of 110 points within 1.88,138.11 6.45,147.4
UG_3V on TOP (solid shape): 281.53,50.24 281.53,49.3 281.44,49.21 280.36,49.21 280.26,49.31 280.26,50.2 280.38,50.32 281.46,50.32
UG_3V on TOP (solid shape): 280.1,60.22 280.1,59.75 280.69,59.16 280.69,58.64 280.59,58.53 279.93,58.53 278.81,59.65 278.81,60.25 278.87,60.3 280.02,60.3
UG_3V on BOTTOM (solid shape): 281.53,50.23 281.53,49.34 281.41,49.21 280.39,49.21 280.26,49.34 280.26,50.23 280.39,50.36 281.41,50.36
UG_3V on BOTTOM (solid shape): 279.98,60.15 279.98,59.8 279.93,59.75 278.8,59.75 278.67,59.88 277.85,59.88 277.79,59.94 277.79,60.07 277.85,60.14 278.87,60.14 278.99,60.26 279.87,60.26
UG_5V on BOTTOM (solid shape): 265.78,52.64 265.78,52.26 265.66,52.13 263.33,52.13 263.23,52.24 263.23,52.74 263.26,52.77 265.66,52.77
UG_5V on BOTTOM (solid shape): 273.67,60.14 274.67,60.14 274.67,59.88 273.66,59.88 273.53,59.75 272.08,59.75 272,59.84 272,60.17 272.1,60.26 273.54,60.26
UG_5V on IN1 (solid shape): 264.98,52.93 264.98,52.25 264.87,52.13 263.41,52.13 263.31,52.24 263.31,52.97 263.36,53.02 264.9,53.02
UG_5V on IN1 (solid shape): 273.45,60.36 273.45,59.75 273.23,59.53 271.85,59.53 271.7,59.68 271.7,60.36 271.78,60.44 273.38,60.44
UG_+V1.05S_VCCPP on TOP (solid shape): 62.76,23.08 62.76,22.43 62.69,22.35 61.68,22.35 61.44,22.59 61.44,23.06 61.54,23.17 62.67,23.17
UG_+V1.05S_VCCPP on TOP (solid shape): 71.69,14.01 71.69,13.5 71.56,13.37 70.33,13.37 70.14,13.56 70.14,13.98 70.31,14.15 71.55,14.15
UG_+V1.05S_VCCPP on BOTTOM (solid shape): 71.61,13.92 71.61,13.54 71.51,13.44 70.28,13.44 70.19,13.53 69.32,13.53 69.19,13.65 69.19,13.91 69.32,14.03 71.5,14.03
UG_+V1.05S_VCCPP on BOTTOM (solid shape): 61.68,23.31 61.82,23.31 61.95,23.18 62.72,23.18 62.77,23.13 62.77,22.63 62.7,22.56 61.76,22.56 61.57,22.75 61.57,22.92 61.25,23.24 60.6,23.24 60.57,23.26 60.55,23.29 60.55,23.44 60.57,23.48 60.6,23.5 61.49,23.5
UG_+V1.05SP on TOP (solid shape): 5.32,152.15 5.36,152.13 5.37,152.1 5.37,151.32 5.56,151.13 5.94,151.13 6.07,151 6.07,150.7 6.04,150.65 6.01,150.59 5.99,150.57 5.96,150.56 5.69,150.56 5.59,150.66 5.5,150.78 5.38,150.87 5.05,151.19 5.05,152.08 5.12,152.15
UG_+V1.05SP on BOTTOM (solid shape): 5.05,147.13 5.05,146.75 4.93,146.62 4.16,146.62 3.97,146.81 3.97,147.51 4.1,147.64 4.55,147.64
UGATE1 on TOP (solid shape): 37.06,64.12 37.06,63.23 36.93,63.1 35.41,63.1 35.28,63.23 35.28,64.12 35.41,64.25 36.93,64.25
UGATE1 on TOP (solid shape): 30.07,77.03 30.07,76.77 30.26,76.58 30.26,76.2 30.2,76.14 29.37,76.14 29.12,76.39 29.12,77.03 29.18,77.09 30.01,77.09
UGATE1 on TOP (solid shape): 35.85,58.15 36.93,58.15 37.06,58.02 37.06,57.64 36.8,57.39 35.04,57.39 34.85,57.58 34.85,58.48 35.03,58.67 35.34,58.67
UGATE1 on IN2 (solid shape): 30.23,76.61 30.23,75.13 30.21,75.1 30.2,75.1 30.13,75.07 30.07,75.03 29.21,75.03 29.15,75.09 29.15,76.61 29.28,76.74 30.1,76.74
UGATE1 on IN2 (solid shape): 35.61,64.5 36.8,64.5 37.06,64.25 37.06,58.02 36.58,57.55 35.25,57.55 35.22,57.52 34.95,57.52 34.85,57.62 34.85,58.56 34.95,58.66 35.52,58.66 36.14,59.28 36.17,59.28 36.17,62.8 36.04,62.93 34.39,62.93 34.14,63.18 34.14,64.71 34.26,64.83 35.28,64.83
UGATE1G on TOP (solid shape): 37.06,81.77 37.06,81.27 36.93,81.14 36.42,81.14 36.04,80.76 34.64,80.76 34.52,80.88 34.52,81.22 34.64,81.34 35.53,81.34 36.09,81.9 36.93,81.9
UGATE1G on TOP (solid shape): 29.95,84.07 29.95,82.68 29.25,81.98 28.8,81.98 28.55,81.73 28.55,80.9 28.36,80.9 28.36,81.92 28.74,82.3 28.93,82.3 29.37,82.74 29.37,84.07 29.44,84.14 29.88,84.14
UGATE1G on IN4 (solid shape): 30.83,84.14 30.83,83 29.44,83 29.31,83.12 29.31,84.14 29.44,84.27 30.71,84.27
UGATE1G on IN4 (solid shape): 35.03,81.47 35.79,81.47 35.91,81.34 35.91,80.84 35.79,80.71 34.52,80.71 34.01,81.22 34.01,81.85 34.14,81.98 34.52,81.98
UGATE2 on TOP (solid shape): 37.06,69.84 37.06,69.33 36.8,69.07 34.64,69.07 34.52,69.2 34.52,69.84 34.64,69.96 36.93,69.96
UGATE2 on TOP (solid shape): 31.09,81.6 31.09,81.03 30.14,80.07 29.12,80.07 29.12,80.26 30.01,80.26 30.2,80.46 30.2,81.15 30.71,81.66 31.02,81.66
UGATE2 on TOP (solid shape): 37.13,75.6 37.13,75.07 36.88,74.82 34.94,74.82 34.75,75.01 34.75,75.36 34.82,75.44 35.87,75.44 36.18,75.75 36.99,75.75
UGATE2 on IN2 (solid shape): 32.71,81.98 32.71,81.2 32.47,80.96 31.02,80.96 30.64,80.58 30.33,80.58 30.2,80.71 30.2,81.15 31.19,82.14 32.55,82.14
UGATE2 on IN2 (solid shape): 37.06,75.49 37.06,69.52 36.53,68.99 34.63,68.99 34.45,69.16 34.45,69.96 34.64,70.15 35.79,70.15 36.3,70.66 36.3,74.61 36.04,74.87 34.34,74.87 33.59,75.62 33.59,76.52 33.7,76.63 35.91,76.63
UGATE2G on TOP (solid shape): 37.06,88 37.06,87.36 36.93,87.23 34.77,87.23 34.64,87.36 34.64,88 34.77,88.12 36.93,88.12
UGATE2G on TOP (solid shape): 29.57,89.53 29.57,89.02 29.37,88.82 29.37,88.56 29.31,88.49 28.55,88.49 28.47,88.57 28.47,88.58 28.08,88.98 28.08,89.51 28.17,89.6 29.5,89.6
UGATE2G on IN4 (solid shape): 29.41,89.59 29.41,88.9 29.3,88.79 28.31,88.79 28.18,88.91 28.18,89.59 28.24,89.65 29.35,89.65
UGATE2G on IN4 (solid shape): 35.04,88.09 35.81,88.09 35.96,87.94 35.96,87.27 35.9,87.21 34.67,87.21 33.98,87.9 33.98,88.2 34.36,88.58 34.54,88.58
UGATE3 on TOP (solid shape): 50.01,49.13 50.01,46.98 49.76,46.72 49.25,46.72 49.12,46.85 49.12,49.01 49.38,49.26 49.88,49.26
UGATE3 on TOP (solid shape): 44.42,49.13 44.42,46.99 44.3,46.86 43.22,46.86 43.01,47.07 43.01,48.98 43.15,49.12 43.15,49.13 43.28,49.26 44.3,49.26
UGATE3 on BOTTOM (solid shape): 47.06,45.89 47.06,45.11 46.91,44.96 45.99,44.96 45.88,45.06 45.88,45.24 45.77,45.35 45.58,45.35 45.5,45.43 45.5,45.99 45.58,46.06 46.89,46.06
UGATE3 on IN2 (solid shape): 44.04,48.26 44.04,47.18 44.51,46.71 48.46,46.71 48.93,47.18 48.93,48.13 49.06,48.26 49.88,48.26 50.07,48.07 50.07,45.91 49.62,45.45 43.48,45.45 42.96,45.97 42.96,48.2 43.15,48.39 43.92,48.39
VFB on TOP (solid shape): 180.69,29.34 180.69,28.64 181.33,28 181.33,27.5 181.27,27.43 180.12,27.43 180,27.56 180,29.15 179.49,29.66 178.34,29.66 178.22,29.78 178.22,30.35 178.28,30.42 179.61,30.42
WIRELESS_ON#/OFF on TOP (solid shape): 281.93,10.63 281.93,5.76 281.89,5.72 281.26,5.72 281.16,5.82 281.16,6.55 280.92,6.8 278.85,6.8 278.73,6.92 278.73,10.41 278.95,10.64 281.92,10.64
Z4304 on TOP (solid shape): 194.03,3.62 194.03,1.97 193.9,1.84 192.76,1.84 192.51,2.1 192.51,3.62 192.63,3.75 193.9,3.75
Z4305 on TOP (solid shape): 196.06,3.62 196.06,2.1 195.81,1.84 194.54,1.84 194.41,1.97 194.41,3.62 194.54,3.75 195.93,3.75
Z4306 on TOP (solid shape): 198.09,3.75 198.09,1.97 197.97,1.84 196.57,1.84 196.44,1.97 196.44,3.75 196.57,3.87 197.97,3.87
N17063765 on TOP (solid shape): 17.4,78.6 17.4,75.78 17.66,75.51 18.22,75.51 18.35,75.39 18.35,74.74 18.3,74.69 16.61,74.69 16.46,74.54 16.46,73.84 16.36,73.74 15.63,73.74 15.53,73.84 15.53,74.69 15.02,75.2 15.02,78.68 15.32,78.98 17.02,78.98
N27967271 on BOTTOM (solid shape): 50.01,22.8 50.01,21.78 50.27,21.53 50.27,19.48 50.25,19.45 50.21,19.43 50.06,19.43 50.03,19.45 50.01,19.48 50.01,20.96 48.74,22.23 48.74,22.8 48.93,22.99 49.82,22.99
N34391411 on TOP (solid shape): 184.52,61.67 184.52,61.02 184.34,60.85 182.14,60.85 181.99,61 181.99,61.67 182.13,61.81 184.38,61.81
N47912632 on TOP (solid shape): 33.94,83.06 33.94,82.01 34.14,81.81 34.14,80.71 33.88,80.46 33.25,80.46 32.99,80.71 32.99,81.75 32.82,81.93 32.82,83.07 32.99,83.25 33.76,83.25
N47912886 on TOP (solid shape): 34.01,77.92 34.01,75.5 33.76,75.25 33.12,75.25 32.99,75.38 32.99,77.76 33.28,78.04 33.88,78.04
N47912908 on TOP (solid shape): 32.61,79.38 32.61,78.49 32.42,78.3 31.66,78.3 31.47,78.11 31.22,78.11 31.09,78.23 31.09,78.36 30.96,78.49 29.12,78.49 29.12,78.68 29.69,78.68 29.75,78.74 30.96,78.74 31.09,78.61 31.6,78.61 31.66,78.68 31.66,79.25 31.98,79.57 32.42,79.57
N47912912 on BOTTOM (solid shape): 43.72,44.77 44.68,44.77 44.74,44.71 44.74,44.58 44.68,44.51 43.22,44.51 43.03,44.7 41.76,44.7 41.63,44.83 41.63,45.53 41.76,45.66 42.84,45.66
N47928569 on TOP (solid shape): 28.43,86.17 28.45,86.17 28.47,86.16 28.74,86.04 29.01,86.16 29.03,86.17 29.05,86.17 30.32,86.17 30.33,86.17 30.35,86.16 30.4,86.11 31.34,86.11 31.41,86.04 31.41,85.28 31.15,85.03 28.17,85.03 27.91,85.28 27.91,85.92 28.17,86.17
N47928632 on TOP (solid shape): 34.14,90.3 34.14,89.54 33.88,89.28 33.09,89.28 32.19,88.38 31.84,88.38 31.46,88 30.61,88 30.54,88.06 30.54,88.18 30.62,88.25 31.44,88.25 32.33,89.14 32.33,90.01 32.87,90.55 33.88,90.55
N85750543 on TOP (solid shape): 7.4,149.35 7.4,148.59 7.28,148.46 4.29,148.46 4.23,148.53 4.23,149.42 4.29,149.48 7.28,149.48
N95930610 on BOTTOM (solid shape): 235.04,49.91 235.04,49.34 234.97,49.28 234.08,49.28 233.83,49.02 233.83,48.32 232.33,46.82 232.33,46.72 232.16,46.56 232.02,46.56 231.99,46.59 231.99,47.44 233.2,48.64 233.2,49.91 233.26,49.98 234.97,49.98
N96028042 on TOP (solid shape): 202.09,3.14 202.09,2.06 201.92,1.89 200.69,1.89 200.5,2.07 200.5,3.09 200.85,3.44 201.79,3.44
N141046134 on BOTTOM (solid shape): 227.6,50.02 227.6,49.07 227.49,48.96 225.56,48.96 225.43,49.09 225.43,49.35 226,49.35 226,49.85 225.43,49.85 225.43,50.11 225.44,50.12 227.49,50.12
N141046134 on BOTTOM (solid shape): 229.29,46.06 230.24,46.06 230.27,46.03 230.27,45.86 230.24,45.83 227.53,45.83 227.4,45.96 227.4,46.41 227.56,46.56 228.79,46.56

Small or netless copper shapes (teardrops, artwork), in the pictures only: 169 on TOP, 44 on BOTTOM, 1 on IN2

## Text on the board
Ref Des/Silkscreen Bottom: 1/2 Mini | Memory Module A | Memory Module B | SATA | WLAN | WWAN
User.Comments: LA-7933P | 2012-05-23 | 2013-05-23 | Kerry_tang | QAR10 | 1.0(A00) | +5V_RUN | +3.3V_RUN | +1.05V_M | +1.05V_RUN | +VCC_SA | +VCC_CORE | +VCC_GFXCORE | +5V_ALW | +DOCK_PWR_BAR | +PWR_SRC | GND | +1.5V_MEM | +3.3V_ALW | +1.05V_RUN_VTT
Ref Des/Silkscreen Top: H21 | H24 | H23 | H22 | H25 | Memory Module C | Memory Module D | 1 | EDP | 2 | LVDS | H11 | H12 | 3 | 2ND HDD | MAIN HDD
User.14: 112.30 | 117.77 | 67.42 | 42.56 | 148.63 | 135.63 | 5.75 | 0.00 | 101.52 | 153.20 | 160.33 | 0.49 | 98.63 | 115.35 | 56.05 | 108.21 | 41.05 | 30.25 | 89.10 | 83.92 | 179.27
User.15: 111.57 | 92.40 | 72.20 | 110.45 | 71.80 | 77.52 | 41.55 | 0.00 | 102.02
User.18: {\Fgdt;n}\Ftxt;3.00 | 78.83 | {\Fgdt;n}\Ftxt;1.20 | 62.80 | {\Fgdt;n}\Ftxt;5.20 | {\Fgdt;n}\Ftxt;4.20 | {\Fgdt;n}\Ftxt;6.00 | 150.48 | 137.48 | 19.10 | 79.97 | {\Fgdt;n}\Ftxt;4.00 | 0.00 | {\Fgdt;n}\Ftxt;3.80 | {\Fgdt;n}\Ftxt;7.00 | 84.49 | {\Fgdt;n}\Ftxt;8.00 | {\Fgdt;n}\Ftxt;3.60 | 70.37 | 8.67 | 169.70 | 173.20 | {\Fgdt;n}\Ftxt;6.50 | 0.40 | 25.77 | 154.77 | 119.80 | 81.68 | 75.20 | 68.10 | 66.68 | 65.10 | 160.27 | 63.83 | 52.77 | 49.92 | 37.77 | 34.92 | 13.58 | 0.58 | 4.80 | 11.40 | 7.40 | 3.40 | 163.34 | 88.34 | 13.60 | 161.77 | 43.00 | 18.60 | 23.60 | 85.62 | 95.62 | 70.10 | 75.10 | 90.62 | 80.10 | 89.49 | 97.20 | 79.70 | 74.70 | 3.17 | 142.60 | 147.60 | 149.70 | 151.77 | 162.27 | 3.00 | 163.00 | 168.60 | 171.00 | 173.80 | 170.30 | 4.00
User.19: {\Fgdt;n}\Ftxt;8.00 | 2.52 | {\Fgdt;n}\Ftxt;8.16 | {\Fgdt;n}\Ftxt;10.00 | 0.00 | {\Fgdt;n}\Ftxt;4.00 | {\Fgdt;n}\Ftxt;6.00 | 60.37 | 2.89 | 87.69
User.20: 113.80 | 96.70 | 75.80 | 67.80 | 62.80 | 156.27 | 142.82 | 27.60 | 26.10 | 134.27 | 119.61 | 167.47 | 91.21 | 0.00 | 43.00 | 149.27 | 96.21 | 88.89 | 49.91 | 153.32 | 155.82 | 140.32 | 56.65 | 46.65 | 158.27
User.22: 91.05 | 182.56 | 166.27 | 4.48 | 48.77 | 171.77 | 7.43 | 123.29 | 101.30 | 0.00 | 7.23 | 180.56
User.40: L1-TOP | L2-GND1 | L3-IN1 | L4-VCC | L5-IN2 | L6-IN3 | L7-GND2 | L8-IN4 | L9-GND3 | L10-BOT | LAYER | NAME | 46 ohm | 48 ohm | 10.5mil
User.41: FIGURE | SIZE | 8.0 | 9.0 | 10.0 | 20.0 | 24.0 | 30.0 | 31.0 | 35.0 | 36.0 | 39.0 | 47.0 | 55.0 | 118.0 | 142.0 | 150.0 | 165.0 | 205.0 | 40.0 | 43.0 | 63.0 | 65.0 | 67.0 | 39.0x33.0 | 45.0x37.0 | 55.0x35.0 | 59.0x31.0 | 63.0x24.0 | 75.0x24.0 | 75.0x37.0 | 83.0x39.0 | 94.0x24.0 | 94.0x35.0 | 94.0x39.0 | 96.0x39.0 | 102.0x31.0 | 112.0x39.0 | 118.0x33.0 | 120.0x39.0 | 142.0x118.0 | 67.0x43.0 | DRILL CHART: TOP to BOTTOM | ALL UNITS ARE IN MILS | PLATED | NON-PLATED | QTY | 19 | 851 | 7149 | 39 | 15 | 7 | 18 | 8 | 4 | 16 | 2 | 9 | 1 | 3 | 10
